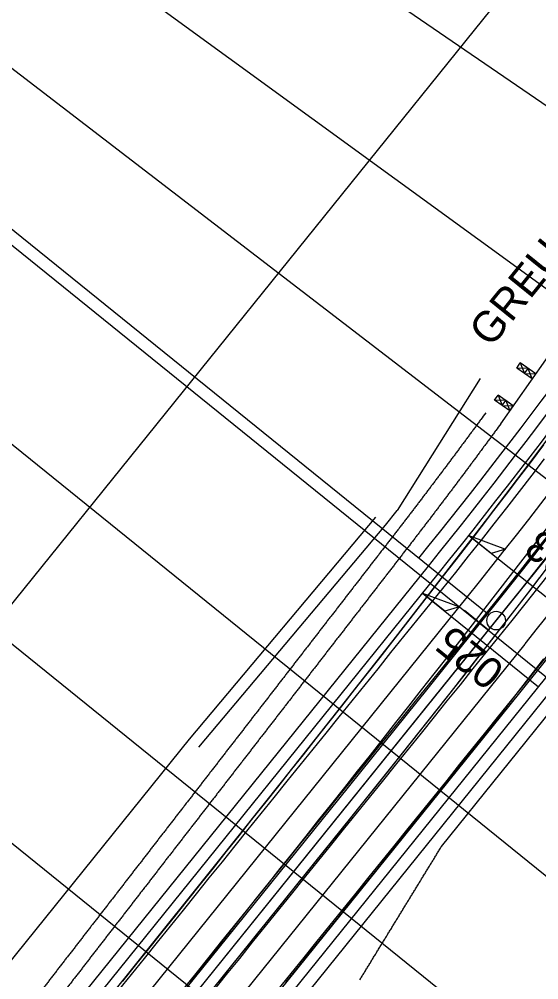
# Model space of a CAD drawing. Extents: x 2293233 to 2294507, y 892788 to 894229.
# Drawn here: x 2293993.2 to 2294077.1, y 893651.6 to 893806.4 of the extents above; entities that cross this region are included whole.
import ezdxf

# ---------------------------------------------------------------- set-up
doc = ezdxf.new("R2010")
doc.units = 0
for name, color, linetype in [('COGO Default Curve', 7, 'Continuous'), ('Prop EOT', 7, 'Continuous'), ('Prop Guardrail', 7, 'Continuous'), ('Prop Guardrail Anchor Unit CELL', 7, 'Continuous'), ('Prop Horizontal Alignment', 7, 'Continuous'), ('Prop Paved Shoulder', 7, 'Continuous'), ('Prop Superelevation  Arrow CELL', 7, 'Continuous'), ('Prop Superelevation Label', 7, 'Continuous'), ('Scratch_Level_0', 7, 'Continuous'), ('Scratch_Level_4', 7, 'Continuous'), ('Scratch_Level_5', 7, 'Continuous')]:
    doc.layers.add(name, color=color, linetype=linetype)

msp = doc.modelspace()

# ---------------------------------------------------------------- linework, layer by layer
at = {"layer": 'COGO Default Curve'}
for p, q in [((2293758.37, 893332.69), (2294065.5, 893713.27)), ((2293767.71, 893325.15), (2294074.84, 893705.73))]:
    msp.add_line(p, q, dxfattribs=at)
for points in [[(2294153.14, 893810.31), (2294150.2, 893805.46), (2294144.41, 893796.11), (2294138.51, 893786.83), (2294132.51, 893777.61), (2294126.4, 893768.47), (2294120.19, 893759.4), (2294113.87, 893750.39), (2294110.57, 893745.78), (2294107.25, 893741.2), (2294103.51, 893736.09), (2294099.53, 893730.74), (2294095.52, 893725.42), (2294091.47, 893720.12), (2294087.39, 893714.85), (2294083.28, 893709.6), (2294078.73, 893703.85), (2294073.94, 893697.86), (2293868.79, 893443.63)], [(2293934.91, 893558.24), (2293982.19, 893616.89), (2294012.67, 893654.83), (2294024.95, 893670.19), (2294035.75, 893683.75), (2294045.26, 893695.77), (2294053.92, 893706.78), (2294061.7, 893716.77), (2294068.83, 893726.01), (2294075.49, 893734.76), (2294081.7, 893743.02), (2294085.47, 893748.1), (2294089.22, 893753.21), (2294092.74, 893758.07), (2294096.24, 893762.94), (2294099.7, 893767.84), (2294102.95, 893772.49), (2294106.35, 893777.42), (2294109.73, 893782.38), (2294113.08, 893787.36), (2294116.39, 893792.36), (2294119.68, 893797.38), (2294123.12, 893802.7), (2294126.34, 893807.75)], [(2294137.26, 893807.39), (2294131.61, 893798.35), (2294125.85, 893789.36), (2294119.8, 893780.17), (2294113.84, 893771.33), (2294107.78, 893762.55), (2294101.61, 893753.84), (2294095.16, 893744.94), (2294091.39, 893739.84), (2294087.6, 893734.78), (2294083.76, 893729.73), (2294079.69, 893724.45), (2294075.59, 893719.2), (2294071.04, 893713.45), (2294059.17, 893698.61), (2294044.74, 893680.7), (2293954.06, 893568.41)], [(2293932.89, 893536.61), (2294046.75, 893677.72), (2294053.42, 893686.04), (2294059.44, 893693.61), (2294065.01, 893700.68), (2294070.34, 893707.51), (2294075.44, 893714.1), (2294080.29, 893720.46), (2294085.11, 893726.85), (2294089.69, 893733), (2294096.97, 893742.96), (2294103.95, 893752.72), (2294107.4, 893757.63), (2294110.82, 893762.56), (2294114.21, 893767.5), (2294117.58, 893772.47), (2294120.92, 893777.46), (2294124.04, 893782.19), (2294127.32, 893787.21), (2294130.39, 893791.98), (2294133.61, 893797.04), (2294136.62, 893801.84), (2294139.78, 893806.94)], [(2294077.8, 893737.81), (2294075.8, 893735.16), (2294073.79, 893732.51), (2294071.78, 893729.87), (2294069.76, 893727.23), (2294067.74, 893724.59), (2294065.71, 893721.95), (2294063.68, 893719.32), (2294061.64, 893716.69), (2294059.6, 893714.06), (2294057.55, 893711.43), (2294055.51, 893708.81), (2294053.45, 893706.19), (2294051.4, 893703.57), (2294049.34, 893700.95), (2294047.29, 893698.33), (2294045.22, 893695.72), (2294043.16, 893693.1), (2294041.09, 893690.49), (2294039.03, 893687.88), (2294036.96, 893685.27), (2294034.89, 893682.66), (2294032.81, 893680.05), (2294030.74, 893677.45), (2294028.66, 893674.84), (2294026.59, 893672.24), (2294024.51, 893669.63), (2294022.43, 893667.03), (2294020.35, 893664.42), (2294018.27, 893661.82), (2294016.19, 893659.22), (2294014.1, 893656.62), (2294012.02, 893654.02), (2294009.93, 893651.42)], [(2294077.93, 893735.58), (2294075.91, 893732.94), (2294073.88, 893730.31), (2294071.84, 893727.69), (2294069.8, 893725.08), (2294067.74, 893722.47), (2294065.67, 893719.87), (2294063.6, 893717.28), (2294061.51, 893714.7), (2294059.43, 893712.11), (2294057.34, 893709.52), (2294055.25, 893706.93), (2294053.16, 893704.34), (2294051.07, 893701.75), (2294048.98, 893699.16), (2294046.88, 893696.57), (2294044.79, 893693.98), (2294042.7, 893691.38), (2294040.61, 893688.79), (2294038.51, 893686.2), (2294036.42, 893683.61), (2294034.33, 893681.01), (2294032.24, 893678.42), (2294030.14, 893675.83), (2294028.05, 893673.23), (2294025.96, 893670.64), (2294023.86, 893668.04), (2294021.77, 893665.45), (2294019.68, 893662.86), (2294017.58, 893660.26), (2294015.49, 893657.67), (2294013.4, 893655.07), (2294011.3, 893652.48), (2294009.21, 893649.89)], [(2294078.54, 893724.71), (2294076.51, 893722.06), (2294074.48, 893719.41), (2294072.44, 893716.76), (2294070.4, 893714.12), (2294068.36, 893711.48), (2294066.31, 893708.84), (2294064.26, 893706.21), (2294062.2, 893703.58), (2294060.15, 893700.95), (2294058.09, 893698.32), (2294056.03, 893695.7), (2294053.96, 893693.07), (2294051.9, 893690.45), (2294049.83, 893687.83), (2294047.76, 893685.22), (2294045.69, 893682.6), (2294043.62, 893679.99), (2294041.54, 893677.37), (2294039.47, 893674.76), (2294037.39, 893672.15), (2294035.31, 893669.54), (2294033.23, 893666.94), (2294031.15, 893664.33), (2294029.07, 893661.72), (2294026.99, 893659.12), (2294024.9, 893656.51), (2294022.82, 893653.91), (2294020.74, 893651.3)], [(2294078.23, 893722.87), (2294076.16, 893720.24), (2294074.09, 893717.61), (2294072.01, 893714.99), (2294069.91, 893712.37), (2294067.81, 893709.77), (2294065.71, 893707.17), (2294063.62, 893704.56), (2294061.52, 893701.96), (2294059.42, 893699.37), (2294057.32, 893696.77), (2294055.23, 893694.17), (2294053.13, 893691.57), (2294051.04, 893688.98), (2294048.94, 893686.38), (2294046.85, 893683.79), (2294044.75, 893681.19), (2294042.66, 893678.59), (2294040.56, 893676), (2294038.47, 893673.4), (2294036.37, 893670.81), (2294034.28, 893668.21), (2294032.19, 893665.62), (2294030.09, 893663.02), (2294028, 893660.43), (2294025.9, 893657.84), (2294023.81, 893655.24), (2294021.72, 893652.65), (2294019.62, 893650.05)], [(2294024.62, 893649.87), (2294026.71, 893652.47), (2294028.81, 893655.06), (2294030.9, 893657.66), (2294032.99, 893660.25), (2294035.09, 893662.85), (2294037.18, 893665.44), (2294039.28, 893668.03), (2294041.37, 893670.63), (2294043.46, 893673.22), (2294045.56, 893675.82), (2294047.65, 893678.41), (2294049.74, 893681.01), (2294051.84, 893683.6), (2294053.93, 893686.19), (2294056.02, 893688.79), (2294058.12, 893691.38), (2294060.21, 893693.98), (2294062.3, 893696.57), (2294064.4, 893699.17), (2294066.49, 893701.76), (2294068.59, 893704.35), (2294070.68, 893706.95), (2294072.77, 893709.54), (2294074.85, 893712.14), (2294076.92, 893714.74), (2294078.98, 893717.35)], [(2294025.48, 893651.33), (2294027.57, 893653.93), (2294029.66, 893656.52), (2294031.76, 893659.12), (2294033.85, 893661.71), (2294035.94, 893664.3), (2294038.04, 893666.9), (2294040.13, 893669.49), (2294042.22, 893672.08), (2294044.31, 893674.68), (2294046.39, 893677.27), (2294048.48, 893679.87), (2294050.56, 893682.47), (2294052.64, 893685.06), (2294054.71, 893687.67), (2294056.79, 893690.27), (2294058.85, 893692.87), (2294060.92, 893695.48), (2294062.98, 893698.09), (2294065.03, 893700.7), (2294067.08, 893703.32), (2294069.12, 893705.94), (2294071.16, 893708.56), (2294073.2, 893711.19), (2294075.22, 893713.82), (2294077.24, 893716.46)], [(2294035.03, 893650.04), (2294037.13, 893652.63), (2294039.22, 893655.23), (2294041.31, 893657.82), (2294043.41, 893660.42), (2294045.5, 893663.01), (2294047.59, 893665.6), (2294049.69, 893668.2), (2294051.78, 893670.79), (2294053.88, 893673.39), (2294055.97, 893675.98), (2294058.06, 893678.58), (2294060.16, 893681.17), (2294062.25, 893683.76), (2294064.34, 893686.36), (2294066.44, 893688.95), (2294068.53, 893691.55), (2294070.62, 893694.14), (2294072.72, 893696.74), (2294074.81, 893699.33), (2294076.9, 893701.92), (2294079, 893704.52)], [(2294036.28, 893651.18), (2294038.37, 893653.78), (2294040.46, 893656.37), (2294042.56, 893658.97), (2294044.65, 893661.56), (2294046.74, 893664.16), (2294048.84, 893666.75), (2294050.93, 893669.35), (2294053.02, 893671.95), (2294055.11, 893674.55), (2294057.19, 893677.15), (2294059.28, 893679.76), (2294061.36, 893682.37), (2294063.44, 893684.98), (2294065.51, 893687.59), (2294067.59, 893690.21), (2294069.65, 893692.83), (2294071.72, 893695.45), (2294073.78, 893698.08), (2294075.83, 893700.72), (2294077.88, 893703.35)]]:
    msp.add_lwpolyline(points, dxfattribs=at)
msp.add_circle((2294065.5, 893713.27), 0.0417, dxfattribs=at)
msp.add_circle((2294065.5, 893713.27), 0.0417, dxfattribs=at)
for radius in [944, 956]:
    msp.add_arc((2293330.88, 894306.12), radius, 321.09608, 333.52096, dxfattribs=at)
at = {"layer": 'Prop EOT'}
for p, q in [((2293753.7, 893336.46), (2294060.83, 893717.04)), ((2293753.7, 893336.46), (2294060.83, 893717.04)), ((2293772.37, 893321.38), (2294079.51, 893701.96))]:
    msp.add_line(p, q, dxfattribs=at)
msp.add_arc((2293330.88, 894306.12), 938, 321.09608, 332.80359, dxfattribs=at)
at = {"layer": 'Prop Guardrail'}
for points in [[(2294070.91, 893741.21), (2294070.13, 893740.14), (2294069.73, 893739.61), (2294069.34, 893739.07), (2294068.95, 893738.54), (2294068.55, 893738.01), (2294068.16, 893737.48), (2294067.77, 893736.94), (2294067.37, 893736.41), (2294066.98, 893735.88), (2294066.58, 893735.35), (2294066.19, 893734.82), (2294065.79, 893734.28), (2294065.4, 893733.75), (2294065, 893733.22), (2294064.6, 893732.69), (2294064.2, 893732.16), (2294063.81, 893731.63), (2294063.41, 893731.1), (2294063.01, 893730.57), (2294062.61, 893730.05), (2294062.21, 893729.52), (2294061.81, 893728.99), (2294061.41, 893728.46), (2294061.01, 893727.93), (2294060.61, 893727.4), (2294060.21, 893726.88), (2294059.81, 893726.35), (2294059.41, 893725.82), (2294059, 893725.3), (2294058.6, 893724.77), (2294058.2, 893724.25), (2294057.79, 893723.72), (2294057.39, 893723.19), (2294056.99, 893722.67), (2294056.58, 893722.14), (2294056.18, 893721.62), (2294055.77, 893721.1), (2294055.36, 893720.56), (2294054.94, 893720.03), (2294054.53, 893719.49), (2294054.12, 893718.96), (2294053.7, 893718.42), (2294053.29, 893717.89), (2294052.87, 893717.36), (2294052.46, 893716.82), (2294052.05, 893716.29), (2294051.63, 893715.75), (2294051.22, 893715.22), (2294050.81, 893714.68), (2294050.39, 893714.15), (2294049.98, 893713.62), (2294049.56, 893713.08), (2294049.15, 893712.55), (2294048.74, 893712.01), (2294048.32, 893711.48), (2294047.91, 893710.94), (2294047.49, 893710.41), (2294047.08, 893709.88), (2294046.67, 893709.34), (2294046.25, 893708.81), (2294045.84, 893708.27), (2294045.43, 893707.74), (2294045.01, 893707.2), (2294044.6, 893706.67), (2294044.18, 893706.14), (2294043.77, 893705.6), (2294043.36, 893705.07), (2294042.94, 893704.53), (2294042.53, 893704), (2294042.12, 893703.46), (2294041.7, 893702.93), (2294041.29, 893702.4), (2294040.87, 893701.86)], [(2294040.87, 893701.86), (2294040.46, 893701.33), (2294040.05, 893700.79), (2294039.63, 893700.26), (2294039.22, 893699.72), (2294038.8, 893699.19), (2294038.39, 893698.66), (2294037.98, 893698.12), (2294037.56, 893697.59), (2294037.15, 893697.05), (2294036.74, 893696.52), (2294036.32, 893695.98), (2294035.91, 893695.45), (2294035.49, 893694.92), (2294035.08, 893694.38), (2294034.67, 893693.85), (2294034.25, 893693.31), (2294033.84, 893692.78), (2294033.42, 893692.24), (2294033.01, 893691.71), (2294032.6, 893691.17), (2294032.18, 893690.64), (2294031.77, 893690.11), (2294031.36, 893689.57), (2294030.94, 893689.04), (2294030.53, 893688.5), (2294030.11, 893687.97), (2294029.7, 893687.43), (2294029.29, 893686.9), (2294028.87, 893686.37), (2294028.46, 893685.83), (2294028.05, 893685.3), (2294027.63, 893684.76), (2294027.22, 893684.23), (2294026.8, 893683.69), (2294026.39, 893683.16), (2294025.98, 893682.63), (2294025.56, 893682.09), (2294025.15, 893681.56), (2294024.73, 893681.02), (2294024.32, 893680.49), (2294023.91, 893679.95), (2294023.49, 893679.42), (2294023.08, 893678.89), (2294022.67, 893678.35), (2294022.25, 893677.82), (2294021.84, 893677.28), (2294021.42, 893676.75), (2294021.01, 893676.21), (2294020.6, 893675.68), (2294020.18, 893675.15), (2294019.77, 893674.61), (2294019.35, 893674.08), (2294018.94, 893673.54), (2294018.53, 893673.01), (2294018.11, 893672.47), (2294017.7, 893671.94), (2294017.29, 893671.41), (2294016.87, 893670.87), (2294016.46, 893670.34), (2294016.04, 893669.8), (2294015.63, 893669.27), (2294015.22, 893668.73), (2294014.8, 893668.2), (2294014.39, 893667.67), (2294013.98, 893667.13), (2294013.56, 893666.6), (2294013.15, 893666.06), (2294012.73, 893665.53), (2294012.32, 893664.99), (2294011.91, 893664.46), (2294011.49, 893663.93), (2294011.08, 893663.39), (2294010.66, 893662.86), (2294010.25, 893662.32)], [(2294010.25, 893662.32), (2294009.84, 893661.79), (2294009.42, 893661.25), (2294009.01, 893660.72), (2294008.6, 893660.19), (2294008.18, 893659.65), (2294007.77, 893659.12), (2294007.35, 893658.58), (2294006.94, 893658.05), (2294006.53, 893657.51), (2294006.11, 893656.98), (2294005.7, 893656.45), (2294005.29, 893655.91), (2294004.87, 893655.38), (2294004.46, 893654.84), (2294004.04, 893654.31), (2294003.63, 893653.77), (2294003.22, 893653.24), (2294002.8, 893652.71), (2294002.39, 893652.17), (2294001.97, 893651.64), (2294001.56, 893651.1), (2294001.15, 893650.57), (2294000.73, 893650.03), (2294000.32, 893649.5), (2293999.91, 893648.97), (2293999.49, 893648.43), (2293999.08, 893647.9), (2293998.66, 893647.36), (2293998.25, 893646.83), (2293997.84, 893646.29), (2293997.42, 893645.76), (2293997.01, 893645.23), (2293996.59, 893644.69), (2293996.18, 893644.16), (2293995.77, 893643.62), (2293995.35, 893643.09), (2293994.94, 893642.55), (2293994.53, 893642.02), (2293994.11, 893641.49), (2293993.7, 893640.95), (2293993.28, 893640.42), (2293992.87, 893639.88), (2293992.46, 893639.35), (2293992.04, 893638.81), (2293991.63, 893638.28), (2293991.22, 893637.75), (2293990.8, 893637.21), (2293990.39, 893636.68), (2293989.97, 893636.14), (2293989.56, 893635.61), (2293989.15, 893635.07), (2293988.73, 893634.54), (2293988.32, 893634.01), (2293987.9, 893633.47), (2293987.49, 893632.94), (2293987.08, 893632.4), (2293986.66, 893631.87), (2293986.25, 893631.33), (2293985.84, 893630.8), (2293985.42, 893630.27), (2293985.01, 893629.73), (2293984.59, 893629.2), (2293984.18, 893628.66), (2293983.77, 893628.13), (2293983.35, 893627.59), (2293982.94, 893627.06), (2293982.53, 893626.52), (2293982.11, 893625.99), (2293981.7, 893625.46), (2293981.28, 893624.92), (2293980.87, 893624.39), (2293980.46, 893623.85), (2293980.04, 893623.32), (2293979.63, 893622.78)]]:
    msp.add_spline(points, degree=3, dxfattribs=at)
at = {"layer": 'Prop Guardrail Anchor Unit CELL'}
for p, q in [((2294070.91, 893741.21), (2294097.78, 893779.47)), ((2294073.49, 893750.2), (2294074.07, 893751.02)), ((2294075.99, 893748.45), (2294073.49, 893750.2)), ((2294075.32, 893750.14), (2294073.49, 893750.2)), ((2294076.57, 893749.27), (2294074.07, 893751.02)), ((2294074.07, 893751.02), (2294074.74, 893749.33)), ((2294074.74, 893749.33), (2294075.32, 893750.14)), ((2294075.99, 893748.45), (2294075.32, 893750.14)), ((2294074.74, 893749.33), (2294076.57, 893749.27)), ((2294069.91, 893745.01), (2294070.49, 893745.83)), ((2294072.94, 893744.11), (2294070.49, 893745.83)), ((2294070.49, 893745.83), (2294071.14, 893744.15)), ((2294072.37, 893743.29), (2294069.91, 893745.01)), ((2294071.72, 893744.97), (2294069.91, 893745.01)), ((2294071.14, 893744.15), (2294071.72, 893744.97)), ((2294071.14, 893744.15), (2294072.94, 893744.11)), ((2294072.94, 893744.11), (2294071.72, 893744.97)), ((2294071.72, 893744.97), (2294072.37, 893743.29)), ((2294072.37, 893743.29), (2294072.94, 893744.11))]:
    msp.add_line(p, q, dxfattribs=at)
at = {"layer": 'Prop Horizontal Alignment'}
for p, q in [((2294069, 893710.44), (2293856.16, 893882.21)), ((2294068.94, 893707.98), (2294065.05, 893711.12)), ((2293763.04, 893328.92), (2294070.17, 893709.5)), ((2293763.04, 893328.92), (2294070.17, 893709.5))]:
    msp.add_line(p, q, dxfattribs=at)
msp.add_circle((2294070.17, 893709.5), 1.5, dxfattribs=at)
msp.add_arc((2293330.88, 894306.12), 950, 321.09608, 333.52096, dxfattribs=at)
msp.add_arc((2293330.88, 894306.12), 950, 321.09608, 333.52096, dxfattribs=at)
at = {"layer": 'Prop Paved Shoulder'}
for p, q in [((2293752.14, 893337.71), (2294059.27, 893718.29)), ((2293773.93, 893320.13), (2294081.06, 893700.71))]:
    msp.add_line(p, q, dxfattribs=at)
msp.add_arc((2293330.88, 894306.12), 936, 321.09608, 332.20827, dxfattribs=at)
at = {"layer": 'Prop Superelevation  Arrow CELL'}
for p, q in [((2294065.76, 893723.2), (2294084.57, 893708.29)), ((2294058.32, 893713.92), (2294076.99, 893698.85))]:
    msp.add_line(p, q, dxfattribs=at)
for points in [[(2294065.76, 893723.2), (2294071.71, 893721.04), (2294069.39, 893720.33)], [(2294058.32, 893713.92), (2294064.24, 893711.71), (2294061.92, 893711.02)]]:
    msp.add_lwpolyline(points, close=True, dxfattribs=at)
at = {"layer": 'Scratch_Level_0'}
for p, q in [((2294067.61, 893748.53), (2294054.19, 893727.24)), ((2294052.31, 893724.9), (2294054.19, 893727.24)), ((2294022.22, 893689.12), (2294052.31, 893724.9))]:
    msp.add_line(p, q, dxfattribs=at)
at = {"layer": 'Scratch_Level_4'}
for p, q in [((2293990.19, 893853.01), (2294237.44, 893683.09)), ((2293978.04, 893835.82), (2294220.73, 893659.46)), ((2293965.44, 893818.95), (2294203.4, 893636.27)), ((2293952.21, 893802.18), (2294185.67, 893613.78)), ((2293708.32, 893261.12), (2294130.82, 893784.65)), ((2293936.51, 893782.73), (2294169.97, 893594.32)), ((2293920.81, 893763.27), (2294154.27, 893574.87)), ((2293905.11, 893743.82), (2294138.57, 893555.41))]:
    msp.add_line(p, q, dxfattribs=at)
at = {"layer": 'Scratch_Level_5'}
for p, q in [((2294086.88, 893829.74), (2293945.58, 893654.65)), ((2294020.71, 893690.39), (2294050.79, 893726.18)), ((2294061.37, 893673.12), (2294082.62, 893699.45)), ((2293973.61, 893632.03), (2294020.71, 893690.39))]:
    msp.add_line(p, q, dxfattribs=at)
msp.add_arc((2293330.88, 894306.12), 934, 321.09608, 331.58156, dxfattribs=at)
for points in [[(2294068.49, 893742.98), (2294067.71, 893741.92), (2294067.32, 893741.38), (2294066.92, 893740.85), (2294066.53, 893740.32), (2294066.14, 893739.79), (2294065.75, 893739.26), (2294065.36, 893738.73), (2294064.96, 893738.2), (2294064.57, 893737.67), (2294064.18, 893737.14), (2294063.78, 893736.61), (2294063.39, 893736.08), (2294062.99, 893735.55), (2294062.6, 893735.02), (2294062.2, 893734.49), (2294061.8, 893733.96), (2294061.41, 893733.44), (2294061.01, 893732.91), (2294060.61, 893732.38), (2294060.22, 893731.85), (2294059.82, 893731.33), (2294059.42, 893730.8), (2294059.02, 893730.27), (2294058.62, 893729.75), (2294058.22, 893729.22), (2294057.82, 893728.69), (2294057.42, 893728.17), (2294057.02, 893727.64), (2294056.62, 893727.12), (2294056.22, 893726.6), (2294055.82, 893726.07), (2294055.42, 893725.55), (2294055.01, 893725.02), (2294054.61, 893724.5), (2294054.21, 893723.98), (2294053.8, 893723.45), (2294053.4, 893722.93), (2294052.99, 893722.4), (2294052.57, 893721.86), (2294052.16, 893721.33), (2294051.74, 893720.8), (2294051.33, 893720.26), (2294050.92, 893719.73), (2294050.5, 893719.19), (2294050.09, 893718.66), (2294049.67, 893718.12), (2294049.26, 893717.59), (2294048.85, 893717.06), (2294048.43, 893716.52), (2294048.02, 893715.99), (2294047.61, 893715.45), (2294047.19, 893714.92), (2294046.78, 893714.38), (2294046.36, 893713.85), (2294045.95, 893713.32), (2294045.54, 893712.78), (2294045.12, 893712.25), (2294044.71, 893711.71), (2294044.3, 893711.18), (2294043.88, 893710.64), (2294043.47, 893710.11), (2294043.05, 893709.58), (2294042.64, 893709.04), (2294042.23, 893708.51), (2294041.81, 893707.97), (2294041.4, 893707.44), (2294040.98, 893706.9), (2294040.57, 893706.37), (2294040.16, 893705.84), (2294039.74, 893705.3), (2294039.33, 893704.77), (2294038.92, 893704.23), (2294038.5, 893703.7)], [(2294038.5, 893703.7), (2294038.09, 893703.16), (2294037.67, 893702.63), (2294037.26, 893702.09), (2294036.85, 893701.56), (2294036.43, 893701.03), (2294036.02, 893700.49), (2294035.61, 893699.96), (2294035.19, 893699.42), (2294034.78, 893698.89), (2294034.36, 893698.35), (2294033.95, 893697.82), (2294033.54, 893697.29), (2294033.12, 893696.75), (2294032.71, 893696.22), (2294032.29, 893695.68), (2294031.88, 893695.15), (2294031.47, 893694.61), (2294031.05, 893694.08), (2294030.64, 893693.55), (2294030.23, 893693.01), (2294029.81, 893692.48), (2294029.4, 893691.94), (2294028.98, 893691.41), (2294028.57, 893690.87), (2294028.16, 893690.34), (2294027.74, 893689.81), (2294027.33, 893689.27), (2294026.91, 893688.74), (2294026.5, 893688.2), (2294026.09, 893687.67), (2294025.67, 893687.13), (2294025.26, 893686.6), (2294024.85, 893686.07), (2294024.43, 893685.53), (2294024.02, 893685), (2294023.6, 893684.46), (2294023.19, 893683.93), (2294022.78, 893683.39), (2294022.36, 893682.86), (2294021.95, 893682.33), (2294021.54, 893681.79), (2294021.12, 893681.26), (2294020.71, 893680.72), (2294020.29, 893680.19), (2294019.88, 893679.65), (2294019.47, 893679.12), (2294019.05, 893678.59), (2294018.64, 893678.05), (2294018.22, 893677.52), (2294017.81, 893676.98), (2294017.4, 893676.45), (2294016.98, 893675.91), (2294016.57, 893675.38), (2294016.16, 893674.85), (2294015.74, 893674.31), (2294015.33, 893673.78), (2294014.91, 893673.24), (2294014.5, 893672.71), (2294014.09, 893672.17), (2294013.67, 893671.64), (2294013.26, 893671.11), (2294012.85, 893670.57), (2294012.43, 893670.04), (2294012.02, 893669.5), (2294011.6, 893668.97), (2294011.19, 893668.43), (2294010.78, 893667.9), (2294010.36, 893667.37), (2294009.95, 893666.83), (2294009.53, 893666.3), (2294009.12, 893665.76), (2294008.71, 893665.23), (2294008.29, 893664.69), (2294007.88, 893664.16)], [(2294048.19, 893651.62), (2294048.37, 893651.91), (2294048.55, 893652.2), (2294048.73, 893652.49), (2294048.91, 893652.78), (2294049.08, 893653.07), (2294049.26, 893653.36), (2294049.44, 893653.65), (2294049.62, 893653.94), (2294049.8, 893654.23), (2294049.97, 893654.52), (2294050.15, 893654.81), (2294050.33, 893655.11), (2294050.51, 893655.4), (2294050.69, 893655.69), (2294050.86, 893655.98), (2294051.04, 893656.27), (2294051.22, 893656.56), (2294051.4, 893656.85), (2294051.58, 893657.14), (2294051.75, 893657.43), (2294051.93, 893657.72), (2294052.11, 893658.01), (2294052.29, 893658.3), (2294052.47, 893658.59), (2294052.64, 893658.88), (2294052.82, 893659.17), (2294053, 893659.46), (2294053.18, 893659.75), (2294053.36, 893660.04), (2294053.53, 893660.33), (2294053.71, 893660.62), (2294053.89, 893660.91), (2294054.07, 893661.21), (2294054.25, 893661.5), (2294054.42, 893661.79), (2294054.6, 893662.08), (2294054.78, 893662.37), (2294054.96, 893662.66), (2294055.14, 893662.95), (2294055.31, 893663.24), (2294055.49, 893663.53), (2294055.67, 893663.82), (2294055.85, 893664.11), (2294056.03, 893664.4), (2294056.2, 893664.69), (2294056.38, 893664.98), (2294056.56, 893665.27), (2294056.74, 893665.56), (2294056.92, 893665.85), (2294057.09, 893666.14), (2294057.27, 893666.43), (2294057.45, 893666.72), (2294057.63, 893667.02), (2294057.81, 893667.31), (2294057.98, 893667.6), (2294058.16, 893667.89), (2294058.34, 893668.18), (2294058.52, 893668.47), (2294058.7, 893668.76), (2294058.87, 893669.05), (2294059.05, 893669.34), (2294059.23, 893669.63), (2294059.41, 893669.92), (2294059.59, 893670.21), (2294059.76, 893670.5), (2294059.94, 893670.79), (2294060.12, 893671.08), (2294060.3, 893671.37), (2294060.48, 893671.66), (2294060.65, 893671.95), (2294060.83, 893672.24), (2294061.01, 893672.53), (2294061.37, 893673.12)], [(2294007.88, 893664.16), (2294007.47, 893663.63), (2294007.05, 893663.09), (2294006.64, 893662.56), (2294006.22, 893662.02), (2294005.81, 893661.49), (2294005.4, 893660.95), (2294004.98, 893660.42), (2294004.57, 893659.89), (2294004.15, 893659.35), (2294003.74, 893658.82), (2294003.33, 893658.28), (2294002.91, 893657.75), (2294002.5, 893657.21), (2294002.09, 893656.68), (2294001.67, 893656.15), (2294001.26, 893655.61), (2294000.84, 893655.08), (2294000.43, 893654.54), (2294000.02, 893654.01), (2293999.6, 893653.47), (2293999.19, 893652.94), (2293998.78, 893652.41), (2293998.36, 893651.87), (2293997.95, 893651.34), (2293997.53, 893650.8), (2293997.12, 893650.27), (2293996.71, 893649.73), (2293996.29, 893649.2), (2293995.88, 893648.67), (2293995.46, 893648.13), (2293995.05, 893647.6), (2293994.64, 893647.06), (2293994.22, 893646.53), (2293993.81, 893645.99), (2293993.4, 893645.46), (2293992.98, 893644.93), (2293992.57, 893644.39), (2293992.15, 893643.86), (2293991.74, 893643.32), (2293991.33, 893642.79), (2293990.91, 893642.25), (2293990.5, 893641.72), (2293990.08, 893641.19), (2293989.67, 893640.65), (2293989.26, 893640.12), (2293988.84, 893639.58), (2293988.43, 893639.05), (2293988.02, 893638.51), (2293987.6, 893637.98), (2293987.19, 893637.44), (2293986.77, 893636.91), (2293986.36, 893636.38), (2293985.95, 893635.84), (2293985.53, 893635.31), (2293985.12, 893634.77), (2293984.71, 893634.24), (2293984.29, 893633.7), (2293983.88, 893633.17), (2293983.46, 893632.64), (2293983.05, 893632.1), (2293982.64, 893631.57), (2293982.22, 893631.03), (2293981.81, 893630.5), (2293981.39, 893629.96), (2293980.98, 893629.43), (2293980.57, 893628.9), (2293980.15, 893628.36), (2293979.74, 893627.83), (2293979.33, 893627.29), (2293978.91, 893626.76), (2293978.5, 893626.22), (2293978.08, 893625.69), (2293977.67, 893625.16), (2293977.26, 893624.62)]]:
    msp.add_spline(points, degree=3, dxfattribs=at)

# ---------------------------------------------------------------- texts
at = {"layer": 'Prop Guardrail Anchor Unit CELL'}
msp.add_text('GREU TL-3', height=5, rotation=51.0748, dxfattribs=at).set_placement((2294069.33, 893753.35))
at = {"layer": 'Prop Superelevation Label'}
for s, rotation, p in [('03', 141.5783, (2294083.27, 893719.82)), ('025', 141.0961, (2294071.82, 893701.94))]:
    msp.add_text(s, height=5, rotation=rotation, dxfattribs=at).set_placement(p)

doc.saveas('drawing.dxf')
